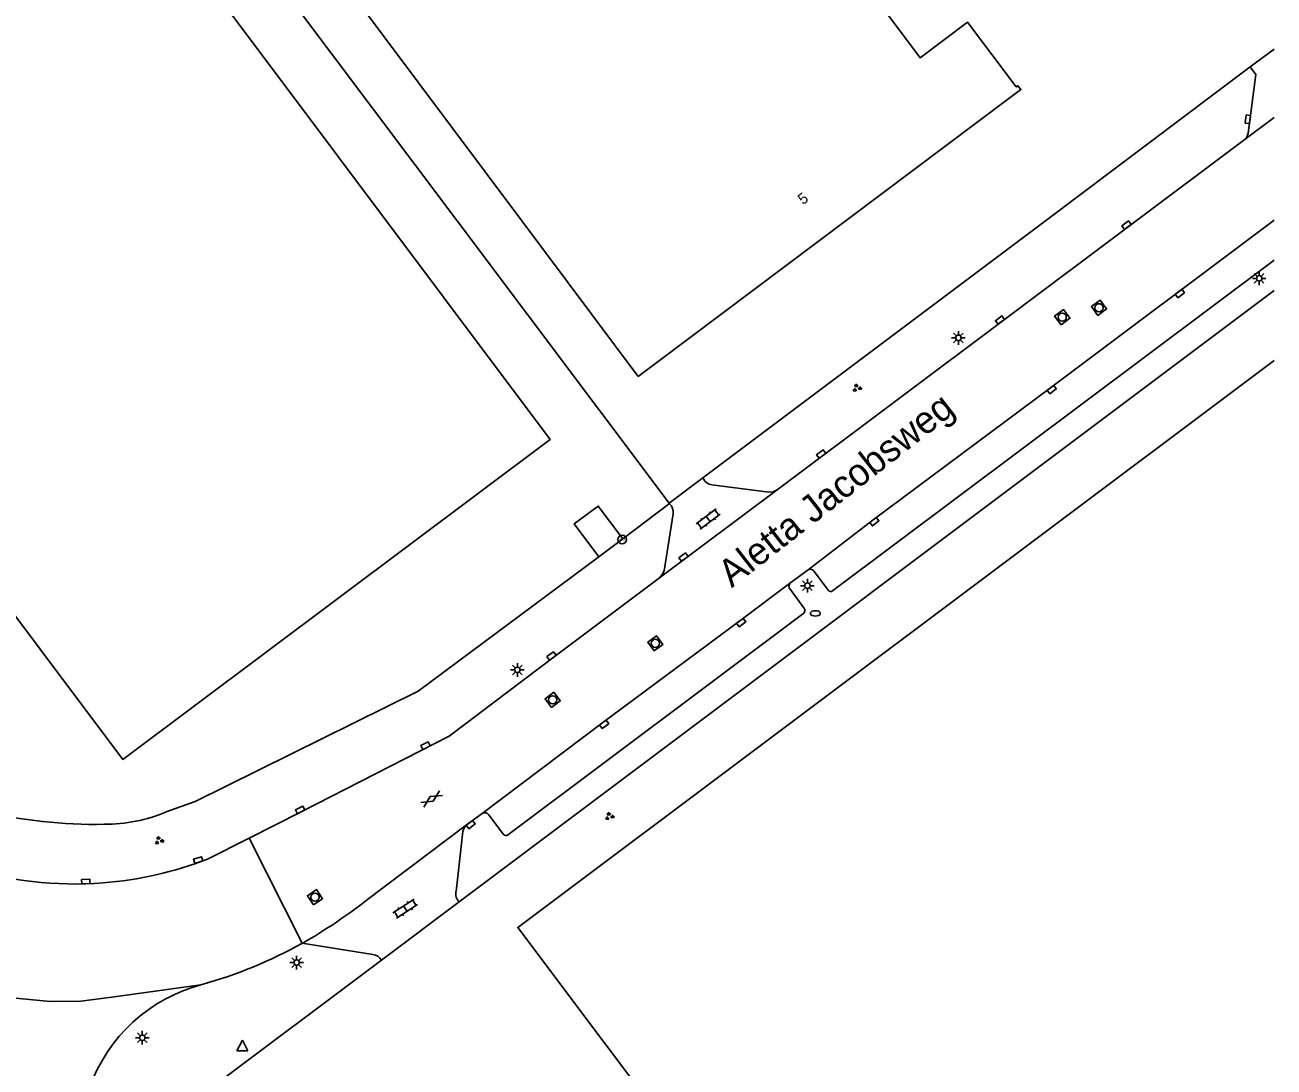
# Model space of a CAD drawing. Extents: x 126000 to 131009, y 393000 to 395500.
# Drawn here: x 130885.3 to 131000, y 393922.3 to 394018 of the extents above; entities that cross this region are included whole.
import ezdxf

# ---------------------------------------------------------------- set-up
doc = ezdxf.new("R2010")
doc.units = 0
for name, color, linetype in [('gg-afsc-hekwerk', 7, 'Continuous'), ('gg-anno-huisnummerreeks BGT', 7, 'Continuous'), ('gg-anno-openbare ruimte label', 7, 'Continuous'), ('gg-bbg-bijgebouw', 7, 'Continuous'), ('gg-bbg-hoofdgebouw', 7, 'Continuous'), ('gg-knt-verharding', 7, 'Continuous'), ('gt-grn-weggrens', 7, 'Continuous'), ('gt-symb-brandkraan', 7, 'Continuous'), ('gt-symb-gesloten verharding', 7, 'Continuous'), ('gt-symb-groenvak', 7, 'Continuous'), ('gt-symb-hoogtemerk', 7, 'Continuous'), ('gt-symb-klinker verharding', 7, 'Continuous'), ('gt-symb-kolk', 7, 'Continuous'), ('gt-symb-lichtmast', 7, 'Continuous'), ('gt-symb-rioolschacht', 7, 'Continuous'), ('gt-symb-waterafsluiter', 7, 'Continuous')]:
    doc.layers.add(name, color=color, linetype=linetype)

# ---------------------------------------------------------------- blocks, each defined once
blk = doc.blocks.new('gt0-HMERK')
at = {"layer": 'gt-symb-hoogtemerk'}
blk.add_circle((0, 0), 0.4, dxfattribs=at)
blk.add_text('N.A.P', height=0.2, dxfattribs=at).set_placement((-0.35, -0.1))
blk = doc.blocks.new('gt0-KOLK')
at = {"layer": 'gt-symb-kolk'}
blk.add_lwpolyline([(0, 0), (0.38, 0), (0.38, 0.4), (-0.37, 0.4), (-0.37, 0), (0, 0)], dxfattribs=at)
blk = doc.blocks.new('gt0-KL1')
at = {"layer": 'gt-symb-klinker verharding'}
for p, q in [((-1.15, 0.3), (1.15, 0.3)), ((-1, -0.3), (-1, 0.3)), ((-0.5, 0.3), (-0.5, 0.45)), ((0, -0.3), (0, 0.3)), ((0.5, 0.3), (0.5, 0.45)), ((1, -0.3), (1, 0.3)), ((-1.15, -0.3), (1.15, -0.3)), ((-0.5, -0.45), (-0.5, -0.3)), ((0.5, -0.45), (0.5, -0.3))]:
    blk.add_line(p, q, dxfattribs=at)
blk = doc.blocks.new('gt0-GRVAK')
at = {"layer": 'gt-symb-groenvak'}
for p, q in [((-0.11, 0.19), (-0.23, 0.24)), ((-0.18, 0.15), (0.09, 0.15)), ((-0.09, 0.21), (-0.16, 0.32)), ((-0.05, 0.21), (-0.05, 0.39)), ((0, 0.21), (0.06, 0.32)), ((0.01, 0.19), (0.13, 0.24)), ((0.26, -0.05), (0.2, 0.06)), ((0.3, -0.05), (0.3, 0.13)), ((0.35, -0.05), (0.41, 0.06)), ((-0.25, -0.23), (-0.36, -0.18)), ((-0.32, -0.26), (-0.05, -0.26)), ((-0.23, -0.21), (-0.29, -0.1)), ((-0.18, -0.2), (-0.18, -0.02)), ((-0.14, -0.21), (-0.07, -0.1)), ((-0.12, -0.23), (0, -0.18)), ((0.24, -0.07), (0.12, -0.02)), ((0.17, -0.11), (0.44, -0.11)), ((0.37, -0.07), (0.49, -0.02))]:
    blk.add_line(p, q, dxfattribs=at)
blk = doc.blocks.new('gt0-LMAST')
at = {"layer": 'gt-symb-lichtmast'}
for p, q in [((-0.18, 0.17), (-0.45, 0.44)), ((0, 0.25), (0, 0.62)), ((0.17, 0.17), (0.44, 0.44)), ((-0.25, 0), (-0.63, 0)), ((-0.18, -0.18), (-0.45, -0.45)), ((0, -0.25), (0, -0.63)), ((0.44, -0.45), (0.17, -0.18)), ((0.25, 0), (0.62, 0))]:
    blk.add_line(p, q, dxfattribs=at)
blk.add_circle((0, 0), 0.25, dxfattribs=at)
blk = doc.blocks.new('gt0-RS')
at = {"layer": 'gt-symb-rioolschacht'}
blk.add_lwpolyline([(-0.5, -0.5), (0.5, -0.5), (0.5, 0.5), (-0.5, 0.5)], close=True, dxfattribs=at)
blk.add_circle((0, 0), 0.375, dxfattribs=at)
blk = doc.blocks.new('gt0-BR')
at = {"layer": 'gt-symb-brandkraan'}
for centre, radius, start, end in [((-0.24, 0), 0.206, 107.5669, 252.4331), ((0.6, -2.66), 3, 106.892, 107.5669), ((0, -0.69), 0.938, 73.108, 106.892), ((-0.6, -2.66), 3, 72.4331, 73.108), ((0.24, 0), 0.206, 287.567, 72.4331), ((0.6, 2.66), 3, 252.4331, 253.108), ((0, 0.69), 0.938, 253.108, 286.8921), ((-0.6, 2.66), 3, 286.8921, 287.567)]:
    blk.add_arc(centre, radius, start, end, dxfattribs=at)
blk = doc.blocks.new('gt0-GESVH1')
at = {"layer": 'gt-symb-gesloten verharding'}
for p, q in [((-0.99, -0.26), (0.01, 0.24)), ((0.01, -0.26), (-0.99, 0.24)), ((0.01, 0.24), (1.01, -0.26)), ((1.01, 0.24), (0.01, -0.26))]:
    blk.add_line(p, q, dxfattribs=at)
blk = doc.blocks.new('gt0-WAFSL')
at = {"layer": 'gt-symb-waterafsluiter'}
for p, q in [((-0.5, -0.33), (0, 0.67)), ((0, 0.67), (0.5, -0.33)), ((0.5, -0.33), (-0.5, -0.33))]:
    blk.add_line(p, q, dxfattribs=at)

msp = doc.modelspace()

# ---------------------------------------------------------------- linework, layer by layer
at = {"layer": 'gg-afsc-hekwerk'}
for p, q in [((130925.01, 394000), (130898.6, 394035.15)), ((130997.82, 394014.11), (131000, 394015.75)), ((130997.82, 394014.11), (130979.02, 394000)), ((130944.48, 393974.08), (130925.01, 394000)), ((130979.02, 394000), (130947.56, 393976.39)), ((130925.2, 393937.48), (131000, 393993.58)), ((130947.56, 393976.39), (130944.48, 393974.08)), ((130944.5, 393974.04), (130940.23, 393970.8)), ((130944.5, 393974.04), (130944.48, 393974.08)), ((130925.2, 393937.48), (130918.07, 393932.13))]:
    msp.add_line(p, q, dxfattribs=at)
for points in [[(130898.31, 393945.74), (130900.96, 393946.7), (130921.43, 393956.83), (130938.02, 393969.16)], [(130934.5, 393856.07), (130929.46, 393867.05), (130900.06, 393906.37), (130901.95, 393920.04), (130918.07, 393932.13)]]:
    msp.add_lwpolyline(points, dxfattribs=at)
for centre, radius, start, end in [((130891.83, 393989.31), 44.72, 256.4651, 271.0087), ((130892.7, 393958.98), 14.38, 269.6695, 292.9504)]:
    msp.add_arc(centre, radius, start, end, dxfattribs=at)
at = {"layer": 'gg-bbg-bijgebouw'}
msp.add_line((130940.23, 393970.8), (130938.02, 393969.16), dxfattribs=at)
msp.add_lwpolyline([(130940.23, 393970.8), (130937.97, 393973.81), (130935.77, 393972.17), (130938.02, 393969.16)], dxfattribs=at)
at = {"layer": 'gg-bbg-hoofdgebouw'}
for points in [[(130941.64, 393985.71), (130976.76, 394012.03), (130976.49, 394012.39), (130976.33, 394012.28), (130971.86, 394018.23), (130967.51, 394014.96), (130894.69, 394112.29)], [(130941.64, 393985.71), (130930.94, 394000), (130902.48, 394038.04), (130898.6, 394035.15)], [(130898.55, 394035.11), (130894.48, 394032.08), (130933.55, 393979.93), (130894.32, 393950.55), (130871.54, 393980.92)], [(131000, 393987.17), (130930.57, 393935.13), (130986.79, 393860.26), (131000, 393870.15)]]:
    msp.add_lwpolyline(points, dxfattribs=at)
at = {"layer": 'gg-knt-verharding'}
for p, q in [((130997.22, 394007.38), (131000, 394009.48)), ((130954.38, 393975.3), (130997.22, 394007.38)), ((130959.48, 393966.02), (131000, 393996.37)), ((130947.62, 393976.31), (130947.56, 393976.39)), ((130943.6, 393967.22), (130954.38, 393975.3)), ((130944.52, 393974.01), (130944.5, 393974.04)), ((130957.24, 393967.96), (130955.63, 393966.78)), ((130959.11, 393966.05), (130957.79, 393967.8)), ((130955.57, 393966.18), (130956.9, 393964.38)), ((130956.84, 393963.98), (130929.65, 393943.6)), ((130927.3, 393945.59), (130925.88, 393944.54)), ((130929.27, 393943.65), (130927.93, 393945.46)), ((130925.88, 393944.54), (130916.67, 393937.61)), ((130925.55, 393943.95), (130924.91, 393938.44)), ((130902.1, 393941.4), (130905.92, 393943.33)), ((130910.8, 393933.68), (130917.28, 393932.66))]:
    msp.add_line(p, q, dxfattribs=at)
for points in [[(130997.22, 394007.38), (130997.49, 394007.67), (130997.63, 394008.04), (130998.34, 394013.41), (130997.82, 394014.11)], [(130957.24, 393967.96), (130963.19, 393972.54), (130979.48, 393984.66), (131000, 394000.04)], [(130954.38, 393975.3), (130954.03, 393975.1), (130953.64, 393975.08), (130948.4, 393975.77)], [(130943.6, 393967.22), (130943.84, 393967.52), (130944.02, 393967.86), (130944.83, 393973.11)], [(130905.92, 393943.33), (130910.68, 393945.74), (130924.29, 393952.7), (130933.79, 393959.89), (130943.6, 393967.22)], [(130955.63, 393966.78), (130950.97, 393963.28), (130938.4, 393953.93), (130927.3, 393945.59)]]:
    msp.add_lwpolyline(points, dxfattribs=at)
for centre, radius, start, end in [((130948.5, 393976.74), 0.982, 206.0622, 263.9834), ((130943.78, 393973.25), 1.06, 352.4485, 45.642), ((130957.43, 393967.61), 0.408, 28.4771, 118.7885), ((130955.9, 393966.45), 0.432, 129.4845, 218.7939), ((130959.31, 393966.23), 0.273, 220.9004, 307.4655), ((130956.63, 393964.22), 0.311, 311.1925, 32.3067), ((130889.94, 393972.83), 33.71, 230.3314, 274.3935), ((130927.54, 393945.17), 0.486, 35.9658, 119.6099), ((130926.5, 393943.81), 0.966, 130.4227, 171.5337), ((130929.5, 393943.87), 0.312, 224.133, 299.223), ((130889.93, 393972.86), 33.73, 274.4051, 291.1558), ((130926.03, 393938.24), 1.14, 170.2431, 222.4973), ((130883.65, 393980.47), 54.11, 300.1231, 307.608), ((130889.96, 393971.3), 43.01, 285.549, 298.9903), ((130917.17, 393931.64), 1.02, 28.4139, 83.4996), ((130905.36, 393915.41), 14.96, 105.0044, 160.1172)]:
    msp.add_arc(centre, radius, start, end, dxfattribs=at)
at = {"layer": 'gt-grn-weggrens'}
for p, q in [((130910.8, 393933.68), (130905.92, 393943.33)), ((130893.3, 393928.74), (130901.49, 393929.86))]:
    msp.add_line(p, q, dxfattribs=at)
msp.add_lwpolyline([(130869.88, 393933.15), (130873.16, 393931.6), (130873.84, 393931.32), (130874.28, 393931.07), (130876.2, 393930.33), (130878.65, 393929.62), (130883.23, 393928.75), (130887.65, 393928.33), (130890.48, 393928.36), (130893.3, 393928.74)], dxfattribs=at)

# ---------------------------------------------------------------- block references
at = {"layer": 'gt-symb-brandkraan'}
msp.add_blockref('gt0-BR', (130957.89, 393963.96), dxfattribs=at)
at = {"layer": 'gt-symb-gesloten verharding', "rotation": 31.877816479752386}
msp.add_blockref('gt0-GESVH1', (130922.66, 393946.93), dxfattribs=at)
at = {"layer": 'gt-symb-groenvak'}
for p in [(130961.7, 393984.64), (130938.98, 393945.33), (130897.64, 393943.11)]:
    msp.add_blockref('gt0-GRVAK', p, dxfattribs=at)
at = {"layer": 'gt-symb-hoogtemerk'}
msp.add_blockref('gt0-HMERK', (130940.16, 393970.74), dxfattribs=at)
at = {"layer": 'gt-symb-klinker verharding'}
for p, rotation in [((130948.06, 393972.62), 36.86989764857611), ((130920.25, 393936.86), 32.87978190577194)]:
    msp.add_blockref('gt0-KL1', p, dxfattribs=dict(at, rotation=rotation))
at = {"layer": 'gt-symb-kolk'}
for p, rotation in [((130997.8, 394009.28), 82.18581914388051), ((130986.58, 393999.43), 36.86989764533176), ((130991.24, 393993.48), -143.11880427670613), ((130974.96, 393990.72), 36.86989764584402), ((130979.48, 393984.66), -143.34313883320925), ((130958.55, 393978.42), 36.869897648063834), ((130963.19, 393972.54), -142.46191323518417), ((130945.91, 393968.96), 36.85214302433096), ((130950.97, 393963.28), -144.16307392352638), ((130933.79, 393959.89), 37.03038960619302), ((130938.4, 393953.93), -143.08975322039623), ((130922.19, 393951.63), 27.128766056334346), ((130910.68, 393945.74), 27.12876605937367), ((130926.14, 393944.74), -143.34313883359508), ((130901.29, 393941.13), 16.984732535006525), ((130890.93, 393939.14), 2.7508347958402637)]:
    msp.add_blockref('gt0-KOLK', p, dxfattribs=dict(at, rotation=rotation))
at = {"layer": 'gt-symb-lichtmast'}
for p in [(130998.64, 393994.71), (130971.03, 393989.25), (130957.17, 393966.5), (130930.54, 393958.77), (130910.28, 393931.91), (130896.11, 393925.01)]:
    msp.add_blockref('gt0-LMAST', p, dxfattribs=at)
at = {"layer": 'gt-symb-rioolschacht'}
for p, rotation in [((130983.93, 393992.01), 36.7896996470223), ((130980.56, 393991.15), 36.789699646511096), ((130943.21, 393961.21), 36.789699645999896), ((130933.78, 393956.02), 36.789699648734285), ((130911.97, 393937.91), 33.91251258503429)]:
    msp.add_blockref('gt0-RS', p, dxfattribs=dict(at, rotation=rotation))
at = {"layer": 'gt-symb-waterafsluiter'}
msp.add_blockref('gt0-WAFSL', (130905.3, 393924.13), dxfattribs=at)

# ---------------------------------------------------------------- texts
at = {"layer": 'gg-anno-huisnummerreeks BGT'}
msp.add_text('5', height=1, rotation=36.9, dxfattribs=at).set_placement((130956.76, 394001.42))
at = {"layer": 'gg-anno-openbare ruimte label'}
msp.add_text('Aletta Jacobsweg', height=2.5, rotation=38.1, dxfattribs=at).set_placement((130950.22, 393966.26))

doc.saveas('drawing.dxf')
